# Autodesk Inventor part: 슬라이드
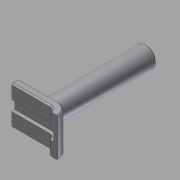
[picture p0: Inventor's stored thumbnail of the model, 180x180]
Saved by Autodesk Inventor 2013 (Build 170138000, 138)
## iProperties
Created: 2015-10
Part Number: 슬라이드
Document SubType Name: Modeling
Designer: mdu
Density: 7.86 g/cm^3
Material: 강철, 연강
Mass: 21.364 g
Surface Area: 19.6411 cm^2
Volume: 2.71806 cm^3
Author: mdu
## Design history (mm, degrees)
sketch "스케치1"
  geometry: L1 (10.279, 23.212)-(25.279, 23.212); L2 (10.279, 19.212)-(25.279, 19.212); L3 (25.279, 26.212)-(10.279, 26.212); L4 (10.279, 26.212)-(10.279, 16.212); L5 (10.279, 16.212)-(25.279, 16.212); C1 r 2 at (25.279, 21.212); A1 r 2 centre (25.279, 21.212) between (25.279, 23.212) and (25.279, 19.212) reference; A2 r 5 centre (25.279, 21.212) between (25.279, 26.212) and (25.279, 16.212); 1 further point
  constraints: 10 end point, 4 point on circle, 4 tangent, 3 parallel, 2 centre point, 2 coincident, 2 point on line, 1 horizontal, 1 perpendicular
  dimensions: "d0" = 4 diameter of C1; "d1" = 10 diameter of A2; "d4" = 15 distance from line of A2.centre L4
extrude "돌출1" new body sketch "스케치1" stored distance "d2" = 15; taper "d3" = 0 deg
sketch "스케치2"
  geometry: L1 (10.279, 26.212)-(10.279, 23.212) reference; L2 (10.279, 24.462)-(25.279, 24.462); L3 (27.779, 19.135)-(27.779, 6.212); L4 (27.779, 6.212)-(0.279, 6.212); L5 (0.279, 6.212)-(0.279, 24.462); L6 (10.279, 24.462)-(0.279, 24.462); A1 r 5 centre (25.279, 21.212) between (25.279, 16.212) and (25.279, 26.212) reference; A2 r 3.25 centre (25.279, 21.212) between (25.279, 24.462) and (27.779, 19.135); 1 further point
  constraints: 10 end point, 4 perpendicular, 2 point on circle, 1 centre point, 1 coincident, 1 parallel, 1 point on line, 1 tangent
  dimensions: "d5" = 6.5 diameter of A2; "d6" = 10 distance between parallel lines of L1 L5; "d7" = 10 distance from line of L4 A1.start; "d8" = 2.5 distance from line of L3 A1.centre
extrude "돌출2" cut sketch "스케치2" stored distance "d9" = 4; taper "d10" = 0 deg
sketch "스케치3"
  geometry: L1 (0, 15)-(0, 0) reference; C1 r 4 at (9.5, 7.5); 2 further points
  constraints: 1 centre point, 1 horizontal alignment, 1 midpoint
  dimensions: "d11" = 8 diameter of C1; "d12" = 9.5 distance from line of C1.centre L1
extrude "돌출3" join sketch "스케치3" distance "d13" = 40; taper "d14" = 0 deg
sketch "스케치4"
  geometry: C1 r 4 at (9.5, 7.5) reference; C2 r 4.65 at (9.5, 7.5); C3 r 6.75 at (9.5, 7.5); C4 r 5.5 at (9.5, 7.5); 1 further point
  constraints: 3 centre point, 3 coincident
  dimensions: "d15" = 9.3 diameter of C2; "d16" = 13.5 diameter of C3; "d19" = 11 diameter of C4
extrude "돌출4" cut sketch "스케치4" distance "d17" = 0.5; taper "d18" = 0 deg
sketch "스케치5"
  geometry: L1 (30.279, 21.212)-(7.279, 21.212); L2 (7.279, 21.212)-(7.279, 13.212); L3 (7.279, 13.212)-(31.947, 13.212); L4 (31.947, 13.212)-(31.947, 21.212); L5 (31.947, 21.212)-(30.279, 21.212); L6 (10.279, 16.212)-(10.279, 19.212) reference; A1 r 5 centre (25.279, 21.212) between (25.279, 16.212) and (25.279, 26.212) reference; 1 further point
  constraints: 10 end point, 2 perpendicular, 1 collinear, 1 horizontal, 1 parallel, 1 point on circle
  dimensions: "d20" = 3 distance between parallel lines of L2 L6; "d21" = 8 distance of L3.end L4.end
extrude "돌출5" cut sketch "스케치5" stored distance "d22" = 1; taper "d23" = 0 deg
chamfer "모따기1" distance "d24" = 0.5; stored, may be unused: second distance "d25" = 2, angle "d26" = 45 deg
hole "구멍1" diameter "d29" = 3.242; stored, may be unused: countersink angle "d33" = 90 deg, drill point angle "d35" = 118 deg; dims "d27" = 10, "d28" = 10, "d30" = 6, "d31" = 4, "d32" = 2, "d34" = 8
chamfer "모따기2" distance "d36" = 0.5; stored, may be unused: second distance "d37" = 2, angle "d38" = 45 deg
node "솔리드1"
node "참조1"
node "투영된 루프1"
